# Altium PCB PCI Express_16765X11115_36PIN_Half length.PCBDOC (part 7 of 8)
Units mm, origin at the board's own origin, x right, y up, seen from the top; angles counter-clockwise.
Board outline 178 x 110.97 mm, 10 copper layers (Top Layer, Int1 (GND), Int2 (Sign), Int3 (Sign), Int4 (PWR), Int5 (GND), Int6 (Sign), Int7 (Sign), Int8 (GND), Bottom Layer), stack 1.429 mm thick; 528 components, 525 nets, 2272 pads, 1491 vias.
Unrouted connection lines stored in the file: 373.
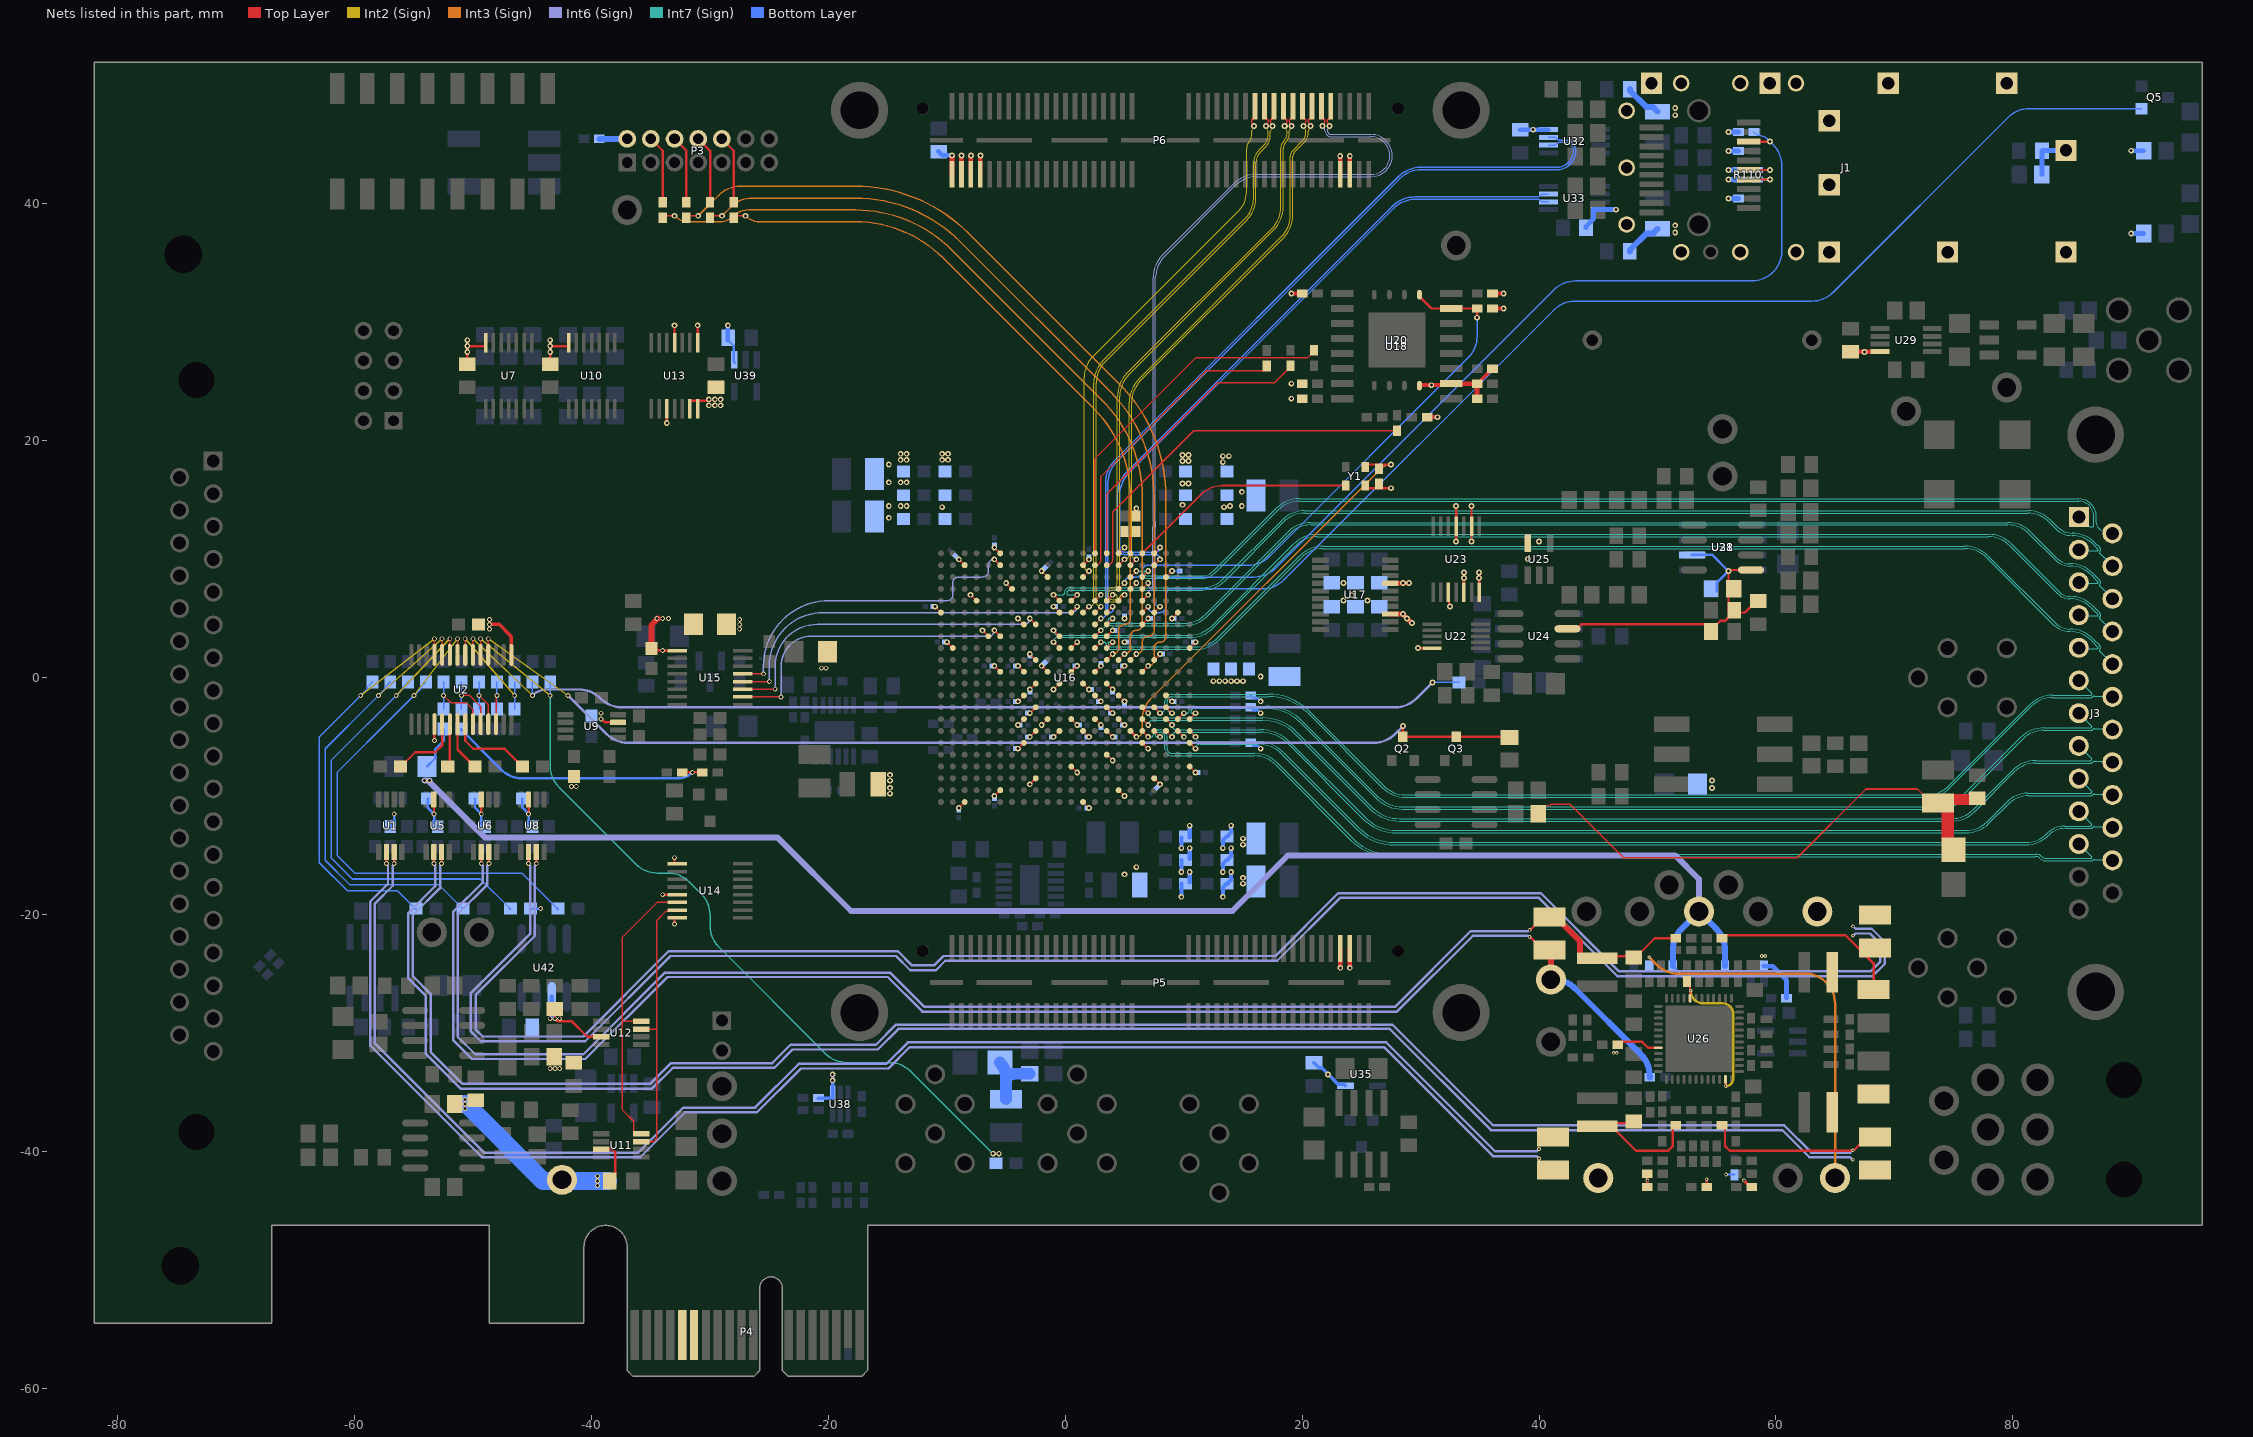
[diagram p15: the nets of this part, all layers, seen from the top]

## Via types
v1: diameter 0.483, hole 0.254, Top Layer to Bottom Layer, tented both sides, 740 vias
v2: diameter 0.508, hole 0.254, Top Layer to Bottom Layer, tented both sides, 302 vias
v3: diameter 0.406, hole 0.254, Top Layer to Bottom Layer, tented both sides, 267 vias
v4: diameter 0.305, hole 0.152, Top Layer to Bottom Layer, tented both sides, 95 vias
v5: diameter 0.5, hole 0.254, Top Layer to Bottom Layer, tented both sides, 50 vias
v6: diameter 0.45, hole 0.254, Top Layer to Bottom Layer, tented both sides, 23 vias
v7: diameter 0.6, hole 0.254, Top Layer to Bottom Layer, tented both sides, 14 vias

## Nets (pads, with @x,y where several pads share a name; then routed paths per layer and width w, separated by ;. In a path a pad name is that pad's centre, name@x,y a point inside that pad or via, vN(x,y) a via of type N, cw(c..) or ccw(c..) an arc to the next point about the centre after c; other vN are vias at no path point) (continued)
S49_64.S60_P: P6.56 U16.N20 | length 46
  Top Layer w0.127: U16.N20@1.5,8.5 v1(2,9) ; v2(15.912,46.6) ccw(c15.732,46.6) 15.859,46.727 15.817,46.77 cw(c16.046,47) 15.721,47 15.721,47.04 cw(c15.873,47.04) 15.766,47.148 cw(c15.838,47.076) 15.838,47.178 ccw(c15.838,47.28) 15.91,47.208 15.95,47.248 ccw(c15.781,47.416) 16.02,47.416 P6.56@16.02,48.245
  Int2 (Sign) w0.076: v1(2,9) cw(c2,9.398) 1.602,9.398 1.602,23.883 1.6,23.884 1.6,25.361 cw(c4.14,25.361) 2.344,27.157 14.679,39.492 ccw(c13.172,40.999) 15.303,40.999 15.303,44.725 cw(c15.975,44.725) 15.5,45.2 15.501,45.201 ccw(c14.97,45.732) 15.721,45.732 15.721,46.14 cw(c16.203,46.14) 15.862,46.48 ccw(c15.743,46.6) v2(15.912,46.6)
S49_64.S61_N: P6.60 U16.P17 | length 49.2
  Top Layer w0.127: U16.P17@2.5,5.5 v1(3,6) ; v2(17.512,46.6) ccw(c17.332,46.6) 17.459,46.727 17.417,46.77 cw(c17.647,47) 17.321,47 17.321,47.04 cw(c17.474,47.04) 17.366,47.148 cw(c17.438,47.076) 17.438,47.178 ccw(c17.438,47.28) 17.51,47.208 17.55,47.248 ccw(c17.381,47.416) 17.62,47.416 P6.60@17.62,48.245
  Int2 (Sign) w0.076: v1(3,6) cw(c3,6.398) 2.602,6.398 2.602,12.5 2.6,12.5 2.6,24.861 cw(c5.14,24.861) 3.344,26.657 15.331,38.644 ccw(c13.475,40.5) 16.1,40.496 ccw(c13.475,40.5) 16.1,40.5 16.1,43.5 cw(c17.338,43.5) 16.462,44.375 16.975,44.888 ccw(c16.14,45.724) 17.321,45.724 17.321,46.14 cw(c17.803,46.14) 17.462,46.48 ccw(c17.343,46.6) v2(17.512,46.6)
S49_64.S61_P: P6.58 U16.N17 | length 49.3
  Top Layer w0.127: U16.N17@1.5,5.5 v1(2,6) ; P6.58@16.82,48.245 16.82,47.416 ccw(c17.058,47.416) 16.89,47.248 16.93,47.208 ccw(c17.002,47.28) 17.002,47.178 cw(c17.002,47.076) 17.074,47.148 cw(c16.966,47.04) 17.118,47.04 17.118,47 cw(c16.793,47) 17.023,46.77 16.98,46.727 ccw(c17.107,46.6) v2(16.928,46.6)
  Int2 (Sign) w0.076: v1(2,6) ccw(c2,6.398) 2.398,6.398 2.398,12.469 ; 2.398,12.471 ccw(c2.322,12.47) 2.398,12.478 cw(c2.6,12.5) 2.397,12.5 2.397,24.862 cw(c5.137,24.862) 3.2,26.8 15.187,38.787 ccw(c13.475,40.5) 15.897,40.5 ; 15.897,40.449 15.897,43.501 cw(c17.335,43.501) 16.318,44.518 16.831,45.031 ccw(c16.14,45.724) 17.118,45.724 17.118,46.14 ccw(c16.637,46.14) 16.977,46.48 cw(c17.097,46.6) v2(16.928,46.6)
S49_64.S62_N: P6.62 U16.T18 | length 50.7
  Top Layer w0.127: U16.T18@4.5,6.5 v1(5,7) ; P6.62@18.42,48.245 18.42,47.416 ccw(c18.658,47.416) 18.489,47.248 18.529,47.208 ccw(c18.601,47.28) 18.601,47.178 cw(c18.601,47.076) 18.673,47.148 cw(c18.566,47.04) 18.718,47.04 18.718,47 cw(c18.393,47) 18.623,46.77 18.58,46.727 ccw(c18.707,46.6) v2(18.528,46.6)
  Int2 (Sign) w0.076: v1(5,7) 4.802,7 ccw(c4.802,6.8) 4.602,6.8 cw(c4.198,6.8) 4.198,6.397 4,6.397 cw(c4,7) 3.397,7 cw(c4,7) 4,7.603 4.003,7.603 ccw(c4.003,8) 4.4,8 4.4,23.765 cw(c7.141,23.765) 5.191,25.69 cw(c7.141,23.765) 5.202,25.702 ; 5.203,25.703 17.453,37.953 ccw(c15.657,39.749) 18.197,39.749 18.197,44.671 cw(c19.225,44.671) 18.498,45.398 18.519,45.419 ccw(c18.037,45.9) 18.718,45.9 18.718,46.14 ccw(c18.237,46.14) 18.577,46.48 cw(c18.697,46.6) v2(18.528,46.6)
S49_64.S62_P: P6.64 U16.R18 | length 50.1
  Top Layer w0.127: U16.R18@3.5,6.5 v1(4,7) ; v2(19.112,46.6) ccw(c18.932,46.6) 19.059,46.727 19.017,46.77 cw(c19.246,47) 18.921,47 18.921,47.04 cw(c19.073,47.04) 18.966,47.148 cw(c19.038,47.076) 19.038,47.178 ccw(c19.038,47.28) 19.11,47.208 19.15,47.248 ccw(c18.981,47.416) 19.22,47.416 P6.64@19.22,48.245
  Int2 (Sign) w0.076: v1(4,7) 4.198,7 cw(c4.198,6.8) 4.398,6.8 cw(c4.198,6.8) 4.198,6.6 4,6.6 cw(c4,7) 3.6,7 cw(c4,7) 4,7.4 4.003,7.4 ccw(c4.003,8) 4.603,8 4.603,23.764 cw(c7.143,23.764) 5.347,25.56 17.597,37.81 ccw(c15.659,39.748) 18.4,39.748 18.4,44.668 cw(c19.232,44.668) 18.644,45.256 18.663,45.275 ccw(c18.038,45.9) 18.921,45.9 18.921,46.14 cw(c19.403,46.14) 19.062,46.48 ccw(c18.943,46.6) v2(19.112,46.6)
S49_64.S63_N: P6.68 U16.U21 | length 45.3
  Top Layer w0.127: U16.U21@5.5,9.5 v1(6,10) ; v2(20.712,46.6) ccw(c20.532,46.6) 20.659,46.727 20.617,46.77 cw(c20.847,47) 20.521,47 20.521,47.04 cw(c20.674,47.04) 20.566,47.148 cw(c20.638,47.076) 20.638,47.178 ccw(c20.638,47.28) 20.71,47.208 20.75,47.248 ccw(c20.581,47.416) 20.82,47.416 P6.68@20.82,48.245
  Int2 (Sign) w0.076: v1(6,10) cw(c6,10.398) 5.602,10.398 5.602,23.262 cw(c8.142,23.262) 6.344,25.057 cw(c8.142,23.262) 6.346,25.058 18.4,37.113 ccw(c16.463,39.051) 19.203,39.051 19.203,44 cw(c19.774,44) 19.37,44.403 20.208,45.241 ccw(c19.45,45.998) 20.521,45.998 20.521,46.14 cw(c21.003,46.14) 20.662,46.48 ccw(c20.543,46.6) v2(20.712,46.6)
S49_64.S63_P: P6.66 U16.T21 | length 45.3
  Top Layer w0.127: U16.T21@4.5,9.5 v1(5,10) ; P6.66@20.02,48.245 20.02,47.416 ccw(c20.258,47.416) 20.09,47.248 20.13,47.208 ccw(c20.202,47.28) 20.202,47.178 cw(c20.202,47.076) 20.274,47.148 cw(c20.166,47.04) 20.318,47.04 20.318,47 cw(c19.993,47) 20.223,46.77 20.18,46.727 ccw(c20.307,46.6) v2(20.128,46.6)
  Int2 (Sign) w0.076: v1(5,10) ccw(c5,10.398) 5.398,10.398 5.398,23.278 cw(c8.103,23.278) 6.19,25.19 ; 6.197,25.197 18.256,37.256 ccw(c16.46,39.052) 19,39.052 19,44.001 cw(c19.771,44.001) 19.226,44.546 20.063,45.383 ccw(c19.446,46) 20.318,46 20.318,46.14 ccw(c19.837,46.14) 20.177,46.48 cw(c20.297,46.6) v2(20.128,46.6)
S49_64.S64_N: P6.70 U16.V19 | length 61.4
  Top Layer w0.127: U16.V19@6.5,7.5 v1(7,8) ; P6.70@21.62,48.245 21.62,47.416 ccw(c21.858,47.416) 21.689,47.248 21.729,47.208 ccw(c21.801,47.28) 21.801,47.178 cw(c21.801,47.076) 21.873,47.148 cw(c21.766,47.04) 21.918,47.04 21.918,47 cw(c21.593,47) 21.823,46.77 21.78,46.727 ccw(c21.907,46.6) v2(21.728,46.6)
  Int6 (Sign) w0.076: v1(7,8) 7,7.802 ccw(c7.2,7.802) 7.2,7.602 ccw(c7.2,7.802) 7.4,7.802 7.4,12.69 cw(c20.914,12.69) 7.408,13.156 7.408,33.76 cw(c10.149,33.76) 8.211,35.698 14.225,41.713 cw(c16.163,39.775) 16.163,42.516 25.853,42.516 ccw(c25.853,44.063) 27.4,44.063 ccw(c25.786,44.063) 25.786,45.676 22.448,45.676 cw(c22.448,46.2) 21.924,46.2 ccw(c21.602,46.2) 21.83,46.428 21.777,46.48 cw(c21.897,46.6) v2(21.728,46.6)
S49_64.S64_P: P6.72 U16.V18 | length 61.7
  Top Layer w0.127: U16.V18@6.5,6.5 v1(7,7) ; v2(22.312,46.6) ccw(c22.132,46.6) 22.259,46.727 22.216,46.77 cw(c22.446,47) 22.121,47 22.121,47.04 cw(c22.273,47.04) 22.166,47.148 cw(c22.238,47.076) 22.238,47.178 ccw(c22.238,47.28) 22.31,47.208 22.35,47.248 ccw(c22.181,47.416) 22.42,47.416 P6.72@22.42,48.245
  Int6 (Sign) w0.076: v1(7,7) 7,7.198 cw(c7.2,7.198) 7.2,7.398 ccw(c7.2,7.802) 7.603,7.802 7.603,12.689 cw(c20.917,12.689) 7.611,13.156 7.611,33.759 cw(c10.151,33.759) 8.355,35.555 14.368,41.568 cw(c16.164,39.772) 16.164,42.312 25.577,42.312 ; v2(22.312,46.6) cw(c22.128,46.6) 22.258,46.47 22.226,46.438 ccw(c22.464,46.2) 22.127,46.2 ccw(c22.448,46.2) 22.448,45.879 25.786,45.879 cw(c25.786,44.063) 27.603,44.063 cw(c25.853,44.063) 25.853,42.312 25.584,42.312
SCL: J1.5 R110.1 | length 2.9
  Top Layer w0.203: J1.5@57.7,42.87 v1(59.5,42.87)
  Bottom Layer w0.203: R110.1@58.45,42.87 v1(59.5,42.87)
SCLK: U11.8 U12.8 U14.14 | length 27.5
  Top Layer w0.127: U11.8@-35.8,-38.5 -36.3,-38.5 -36.437,-38.363 -36.437,-37.463 -37.4,-36.5 -37.4,-26.525 ; U12.8@-35.8,-29.025 -37.4,-29.025 -37.4,-26.525 ; U14.14@-32.775,-18.975 -34.475,-18.975 -37.4,-21.9 -37.4,-26.525
SDA: J1.4 R110.2 | length 2.9
  Top Layer w0.203: J1.4@57.7,42.07 v1(59.5,42.07)
  Bottom Layer w0.203: R110.2@58.45,42.07 v1(59.5,42.07)
SENS1: R5.2 U2.19 | length 6.2
  Top Layer w0.203: R5.2@-56.2,-7.6 -54.9,-6.3 -53.2,-6.3 -52.625,-5.725 U2.19@-52.625,-3.925
SENS2: R6.2 U2.20 | length 3.7
  Top Layer w0.203: R6.2@-52.15,-7.5 -51.975,-7.325 U2.20@-51.975,-3.925 U2.20@-52,-3.9
SENS3: R10.2 U2.21 | length 4.2
  Top Layer w0.203: U2.21@-51.325,-3.925 -51.325,-6.075 R10.2@-49.9,-7.5
SENS4: R12.2 U2.22 | length 7.2
  Top Layer w0.203: U2.22@-50.675,-3.925 -50.672,-3.928 -50.672,-5.328 -50,-6 -47.35,-6 -46.298,-7.052 -46.298,-7.102 -45.9,-7.5 R12.2@-45.85,-7.5
SENS5: R189.2 R190.1 U2.23 | length 6.5
  Top Layer w0.127: v3(-52.5,-1.5) -51.9,-2.1 -50.6,-2.1 -50.025,-2.675 U2.23@-50.025,-3.925
  Bottom Layer w0.127: R189.2@-52.5,-2.65 v3(-52.5,-1.5) R190.1@-52.5,-0.35
SENS6: R186.2 R187.1 U2.24 | length 5.8
  Top Layer w0.127: v3(-51,-1.5) -50.3,-1.5 -49.375,-2.425 U2.24@-49.375,-3.925
  Bottom Layer w0.127: R186.2@-51,-2.65 v3(-51,-1.5) R187.1@-51,-0.35
SENS7: R181.2 R182.1 U2.25 | length 5
  Top Layer w0.127: v3(-49.5,-1.5) -48.725,-2.275 U2.25@-48.725,-3.925
  Bottom Layer w0.127: R181.2@-49.5,-2.65 v3(-49.5,-1.5) R182.1@-49.5,-0.35
SENS8: R175.2 R176.1 U2.26 | length 4.7
  Top Layer w0.127: U2.26@-48.037,-3.837 -48.037,-1.537 v3(-48,-1.5)
  Bottom Layer w0.127: R175.2@-48,-2.65 v3(-48,-1.5) R176.1@-48,-0.35
SENS9: R192.2 R200.1 U2.11 | length 36.1
  Top Layer w0.127: U2.11@-53.275,1.925 v3(-53.275,3.287)
  Int2 (Sign) w0.127: v3(-59.5,-1.5) v3(-53.275,3.287)
  Bottom Layer w0.127: R200.1@-58.5,-0.35 -58.937,-0.787 -58.937,-0.937 -63,-5 -63,-7.5 -63,-15.621 -60.621,-18 -56.4,-18 R192.2@-54.9,-19.5
  Bottom Layer w0.203: R192.2@-54.9,-19.5 R192.2@-54.85,-19.5
SENS10: R180.2 R198.1 U2.10 | length 39.2
  Top Layer w0.127: U2.10@-52.625,1.925 v3(-52.625,3.287)
  Int2 (Sign) w0.127: v3(-58,-1.5) v3(-52.625,3.287)
  Bottom Layer w0.127: R198.1@-57,-0.35 -57.437,-0.787 -57.437,-0.937 -58.5,-2 -62.5,-6 -62.5,-15.414 -60.414,-17.5 -52.9,-17.5 R180.2@-50.9,-19.5
  Bottom Layer w0.203: R180.2@-50.9,-19.5 R180.2@-50.85,-19.5
SENS11: R168.2 R195.1 U2.9 | length 42.4
  Top Layer w0.127: U2.9@-51.975,1.925 v3(-51.975,3.287)
  Int2 (Sign) w0.127: v3(-56.5,-1.5) v3(-51.975,3.287)
  Bottom Layer w0.127: R195.1@-55.5,-0.35 -55.937,-0.787 -55.937,-0.937 -62,-7 -62,-8.3 -62,-15.207 -60.207,-17 -49.4,-17 R168.2@-46.9,-19.5
  Bottom Layer w0.203: R168.2@-46.9,-19.5 R168.2@-46.85,-19.5
SENS12: R159.2 R193.1 U2.8 | length 45.7
  Top Layer w0.127: U2.8@-51.325,1.925 v3(-51.325,3.287)
  Int2 (Sign) w0.127: v3(-55,-1.5) v3(-51.325,3.287)
  Bottom Layer w0.127: R193.1@-54,-0.35 -54.437,-0.787 -54.437,-0.937 -56.5,-3 -61.5,-8 -61.5,-15 -60,-16.5 -45.9,-16.5 R159.2@-42.9,-19.5
  Bottom Layer w0.203: R159.2@-42.9,-19.5 R159.2@-42.85,-19.5
SENS13: R170.2 R171.1 U2.7 | length 10
  Top Layer w0.127: U2.7@-50.675,1.925 v3(-50.675,3.287)
  Int2 (Sign) w0.127: v3(-50.675,3.287) v3(-46.5,-1.5)
  Bottom Layer w0.127: R170.2@-46.5,-2.65 v3(-46.5,-1.5) R171.1@-46.5,-0.35
SENS14: R129.2 R166.1 U2.6 | length 89.2
  Top Layer w0.127: U2.6@-50.025,1.925 v3(-50.025,3.287)
  Int6 (Sign) w0.203: v3(-45,-1.5) cw(c-43.793,-2.707) -43.793,-1 -41.052,-1 cw(c-41.052,-3.54) -39.258,-1.742 cw(c-41.052,-3.54) -39.256,-1.744 ; -39.4,-1.6 -39.256,-1.744 ; v2(31,-0.4) 29.644,-1.756 cw(c27.848,0.04) 27.848,-2.5 -37.448,-2.5 cw(c-37.448,0.04) -39.244,-1.756 -39.256,-1.744
  Int2 (Sign) w0.127: v3(-50.025,3.287) v3(-45,-1.5)
  Bottom Layer w0.127: v3(-45,-1.5) R166.1@-45,-0.35 ; v2(31,-0.4) R129.2@33.25,-0.4
SENS15: R141.2 R162.1 U2.5 | length 69.1
  Top Layer w0.127: U2.5@-49.375,1.925 v3(-49.375,3.287)
  Int2 (Sign) w0.127: v3(-49.375,3.287) v3(-43.5,-1.5)
  Int7 (Sign) w0.127: v3(-43.5,-1.5) -43.5,-7.448 ccw(c-40.96,-7.448) -42.756,-9.244 -36.244,-15.756 ccw(c-34.448,-13.96) -34.448,-16.5 -33.552,-16.5 cw(c-33.552,-19.04) -31.756,-17.244 -30.744,-18.256 cw(c-32.54,-20.052) -30,-20.052 -30,-20.948 ccw(c-27.46,-20.948) -29.256,-22.744 -20.244,-31.756 ccw(c-18.448,-29.96) -18.448,-32.5 -14.852,-32.5 cw(c-14.852,-35.04) -13.056,-33.244 v6(-6.1,-40.2) v6(-5.6,-40.2)
  Bottom Layer w0.127: v3(-43.5,-1.5) R162.1@-43.5,-0.35
SENS16: Q2.3 Q3.3 R45.2 U2.4 | length 92
  Top Layer w0.127: U2.4@-48.725,1.925 v3(-48.725,3.287)
  Top Layer w0.203: v2(28.5,-4.1) Q2.3@28.5,-5 Q3.3@33,-5 R45.2@37.5,-5
  Int6 (Sign) w0.203: v3(-42,-1.5) -38.744,-4.756 ccw(c-36.948,-2.96) -36.948,-5.5 26.048,-5.5 ccw(c26.048,-2.96) 27.844,-4.756 v2(28.5,-4.1)
  Int2 (Sign) w0.127: v3(-48.725,3.287) v3(-42,-1.5)
SENSE.SENS_10_P: C68.1 L4.2 R77.2 R96.1 U5.3 | length 161.1
  Top Layer w0.203: v3(-52.675,-15.7) U5.3@-52.675,-14.725 ; R77.2@55.5,-37.75 55.7,-37.95 55.7,-39.55 56.1,-39.95 66.55,-39.95 67.014,-39.486 67.127,-39.486 67.821,-38.791 R96.1@67.821,-38.678
  Int6 (Sign) w0.203: v3(-52.675,-15.7) -52.675,-15.755 -52.8,-15.88 -52.8,-17.766 -55.1,-20.066 -55.1,-25.2 -53.6,-26.7 -53.6,-31.6 -50.9,-34.3 -35.066,-34.3 -33.312,-32.546 -24.746,-32.546 -23.2,-31 -16,-31 -14.3,-29.3 27.6,-29.3 36.1,-37.8 60.7,-37.8 63,-40.1 66.272,-40.1 66.472,-39.9 v4(66.5,-39.9)
SENSE.SENS_18_P: C46.2 L3.2 R48.1 R68.2 U6.3 | length 129.5
  Top Layer w0.203: v3(-48.675,-15.7) U6.3@-48.675,-14.725 ; v4(39.2,-21.3) 39.219,-21.281 39.269,-21.281 40.35,-20.2 R48.1@40.9,-20.2 ; L3.2@45.973,-23.523 47.875,-23.523 48,-23.648 48.125,-23.648 49.773,-22 51.6,-22 R68.2@51.6,-22.25
  Top Layer w0.5: R48.1@40.9,-20.2 41.45,-20.2 42,-20.75 42,-20.8 43.472,-22.272 43.472,-23.45 43.712,-23.69 L3.2@44.922,-23.69
  Int6 (Sign) w0.203: v3(-48.675,-15.7) -48.675,-15.754 -48.8,-15.879 -48.8,-17.466 -51.3,-19.966 -51.3,-30.334 -49.834,-31.8 -40.7,-31.8 -33.8,-24.9 -14.8,-24.9 -11.9,-27.8 27.832,-27.8 34.232,-21.4 38.5,-21.4 39.073,-21.4 39.173,-21.3 v4(39.2,-21.3)
SENSE.SENS_25_P: C69.2 L5.2 R78.2 R97.1 U8.3 | length 165.9
  Top Layer w0.203: v3(-44.675,-15.7) U8.3@-44.675,-14.725 ; R78.2@55.4,-22 55.4,-21.75 65.875,-21.75 68.25,-24.125 C69.2@68.25,-26.35 ; R78.2@55.45,-22.25 R78.2@55.45,-22
  Int6 (Sign) w0.203: v3(-44.675,-15.7) -44.675,-15.754 -44.8,-15.879 -44.8,-21.8 -49.8,-26.8 -49.8,-29.7 -49.2,-30.3 -40.7,-30.3 -33.5,-23.1 -14.134,-23.1 -12.934,-24.3 -11.1,-24.3 -10.3,-23.5 17.734,-23.5 23.034,-18.2 40.166,-18.2 46.766,-24.8 68,-24.8 68.8,-24 68.8,-22.466 67.934,-21.6 66.728,-21.6 66.528,-21.8 v4(66.5,-21.8)
SENSE.SENS_33_P: C45.2 L2.2 R49.1 R67.2 U1.3 | length 139
  Top Layer w0.203: v3(-56.675,-15.7) U1.3@-56.675,-14.725 ; L2.2@44.237,-38.259 44.646,-37.85 46.102,-37.85 48.2,-39.948 48.2,-39.95 50.9,-39.95 51.3,-39.55 51.3,-38.048 51.599,-37.75 R67.2@51.6,-37.75 ; L2.2@45.973,-37.626 47.848,-37.626 C45.2@48,-37.475
  Int6 (Sign) w0.203: v3(-56.675,-15.7) -56.675,-15.754 -56.8,-15.879 -56.8,-17.566 -58.3,-19.066 -58.3,-30.9 -49.1,-40.1 -36.066,-40.1 -32.266,-36.3 -26.2,-36.3 -22.5,-32.6 -15.1,-32.6 -13.3,-30.8 27.1,-30.8 36.3,-40 39.773,-40 39.973,-39.8 v4(40,-39.8)
SENSE.SENS_120b_P: D2.2 R139.1 R142.1 | length 5.3
  Bottom Layer w1: D2.2@-5.525,-32.5 cw(c-6.792,-33.767) -5,-33.767 ; R142.1@-5,-35.6 -5,-33.767 ; R139.1@-3,-33.45 -4.234,-33.45 ccw(c-4.234,-34.534) -5,-33.767
SENSE.SENS_120x_P: C73.1 D1.2 R46.2 R99.1 | length 46.7
  Top Layer w0.127: R46.2@39.9,-11.5 39.9,-11.45 40.537,-10.813 40.886,-10.813 41,-10.7 42.634,-10.7 47.134,-15.2 61.8,-15.2 67.6,-9.4 71.95,-9.4 73.15,-10.6 R99.1@73.7,-10.6
  Top Layer w0.925: R99.1@74.021,-10.279 76.896,-10.279 C73.1@77,-10.175
  Top Layer w1.07: R99.1@73.7,-10.6 74.25,-10.6 74.515,-10.865 74.515,-14.04 D1.2@75,-14.525
SFP_SH: C75.1 J1.21 J1.22 R107.1 | length 4
  Bottom Layer w0.406: R107.1@82.45,42.5 82.475,42.525 82.475,44.475 82.52,44.52 J1.21@84.5,44.52
SFPIN.LEDIN: Q5.1 U16.V17 | length 102.8
  Top Layer w0.127: U16.V17@6.5,5.5 v1(7,6)
  Bottom Layer w0.127: v1(7,6) ccw(c7.5,6) 7.5,5.5 8,5.5 ccw(c8,6) 8.5,6 8.5,7 cw(c9,7) 9,7.5 16.648,7.5 ccw(c16.648,10.04) 18.444,8.244 41.256,31.056 cw(c43.052,29.26) 43.052,31.8 63.048,31.8 ccw(c63.048,34.34) 64.844,32.544 79.606,47.306 cw(c81.402,45.51) 81.402,48.05 Q5.1@90.875,48.05
SFPIN.LOS: J1.8 R113.1 U16.W17 | length 80.9
  Top Layer w0.127: U16.W17@7.5,5.5 v1(8,6)
  Top Layer w0.203: J1.8@57.7,45.27 v1(59.5,45.27)
  Bottom Layer w0.127: v1(8,6) cw(c8,6.5) 7.5,6.5 7.5,8 cw(c8,8) 8,8.5 15.948,8.5 ccw(c15.948,11.04) 17.744,9.244 20,11.5 37.9,29.4 41.256,32.756 cw(c43.052,30.96) 43.052,33.5 57.96,33.5 ; 58,33.5 57.96,33.5 ; R113.1@58.15,46.07 58.436,45.784 58.589,45.784 cw(c58.589,44.823) 59.268,45.502 v1(59.5,45.27) 59.756,45.014 cw(c57.96,43.218) 60.5,43.218 60.5,36.04 cw(c57.96,36.04) 57.96,33.5
SFPIN.SYNCIN_N: U16.R17 U32.7 | length 67
  Top Layer w0.127: U16.R17@3.5,5.5 v1(4,6)
  Bottom Layer w0.127: v1(4,6) 4,5.7 cw(c3.8,5.7) 3.8,5.5 cw(c3.8,5.698) 3.602,5.698 3.602,16.45 cw(c6.142,16.45) 4.346,18.246 28.253,42.153 cw(c30.049,40.357) 30.049,42.897 41.5,42.897 ccw(c41.5,44.5) 43.103,44.5 ccw(c42.202,44.5) 42.202,45.402 41.721,45.402 cw(c41.721,45.656) 41.542,45.476 41.542,45.479 41.468,45.552 ccw(c41.291,45.375) 41.291,45.625 U32.7@40.805,45.625
SFPIN.SYNCIN_P: U16.P16 U32.6 | length 66.7
  Top Layer w0.127: U16.P16@2.5,4.5 v1(3,5)
  Bottom Layer w0.127: v1(3,5) ccw(c3,5.398) 3.398,5.398 3.398,16.451 cw(c6.139,16.451) 4.201,18.389 28.11,42.297 cw(c30.048,40.359) 30.048,43.1 41.5,43.1 ccw(c41.5,44.5) 42.9,44.5 ccw(c42.202,44.5) 42.202,45.198 41.721,45.198 ccw(c41.721,44.944) 41.542,45.124 41.542,45.121 41.468,45.048 cw(c41.291,45.225) 41.291,44.975 U32.6@40.805,44.975
SFPIN.SYNCOUT_N: U16.W22 U33.2 | length 56
  Top Layer w0.127: U16.W22@7.5,10.5 v1(8,11)
  Bottom Layer w0.127: v1(8,11) cw(c7.602,11) 7.602,10.602 5,10.602 cw(c5,11.002) 4.6,11.002 4.6,15.448 cw(c7.14,15.448) 5.344,17.244 27.754,39.654 cw(c29.551,37.858) 29.551,40.398 39.879,40.398 cw(c39.879,40.144) 40.059,40.324 40.059,40.321 40.132,40.248 ccw(c40.309,40.425) 40.309,40.175 U33.2@40.795,40.175
SFPIN.SYNCOUT_P: U16.W21 U33.3 | length 56.6
  Top Layer w0.127: U16.W21@7.5,9.5 v1(8,10)
  Bottom Layer w0.127: v1(8,10) ccw(c7.602,10) 7.602,10.398 5,10.398 cw(c5,11.002) 4.397,11.002 4.397,15.449 cw(c7.137,15.449) 5.2,17.387 27.612,39.799 cw(c29.549,37.861) 29.549,40.602 39.879,40.602 ccw(c39.879,40.856) 40.059,40.676 40.059,40.679 40.132,40.752 cw(c40.309,40.575) 40.309,40.825 U33.3@40.795,40.825
SMCLK: P4.B5
SMDAT: P4.B6
SQSPI.EMCLK_EN: R38.2 U16.U7 Y1.1 | length 35.1
  Top Layer w0.203: U16.U7@5.5,-4.5 v1(6,-5) ; Y1.1@25.3,17.9 25.4,18 v1(27.5,18)
  Int3 (Sign) w0.127: v1(6,-5) ccw(c6,-4.5) 6.5,-4.5 6.5,-3.552 cw(c9.04,-3.552) 7.244,-1.756 26.646,17.646 cw(c27.5,16.793) v1(27.5,18)
SQSPI.PUDC_B: R28.1 R29.1 U16.U22 | length 2.6
  Top Layer w0.127: R28.1@5.1,12.15 5.5,11.75 ; U16.U22@5.5,10.5 5.5,11.75 ; R29.1@6,12.3 6,12.25 5.5,11.75
SQSPI.QSPI_CS: R42.2 U16.T19 U18.7 U20.1 | length 47.5
  Top Layer w0.127: U16.T19@4.5,7.5 v1(5,8)
  Top Layer w0.203: U20.1@29.905,32.34 29.905,32.193 30.923,31.175 U18.7@32.6,31.175 R42.2@34.77,31.175 34.77,30.473 ccw(c34.873,30.473) v1@34.8,30.4
  Bottom Layer w0.127: v1(5,8) cw(c5.5,8) 5.5,8.5 6,8.5 ccw(c6,9) 6.5,9 cw(c7,9) 7,9.5 15.448,9.5 ccw(c15.448,12.04) 17.244,10.244 34.026,27.026 ccw(c32.23,28.822) 34.77,28.822 v1(34.77,30.4)
SQSPI.QSPI_DQ0: R35.2 U16.P22 | length 30.4
  Top Layer w0.127: U16.P22@2.5,10.5 2.5,13.156 2.5,18.5 11,27 20.45,27 21.1,27.65 R35.2@21.1,27.7
SQSPI.QSPI_DQ1: R31.2 U16.R22 | length 25.1
  Top Layer w0.127: U16.R22@3.5,10.5 3.5,13.156 3.5,15.5 12.9,24.9 17.667,24.9 18.726,25.959 19.012,26.245 R31.2@19.012,26.345
SQSPI.QSPI_DQ2: R30.2 U16.P21 | length 25.5
  Top Layer w0.127: U16.P21@2.5,9.5 ccw(c2.5,10) 3,10 3,13.156 3,17 11.936,25.936 16.963,25.936 R30.2@16.967,25.94
SQSPI.QSPI_DQ3: R39.2 U16.R21 | length 31.6
  Top Layer w0.127: U16.R21@3.5,9.5 ccw(c3.5,10) 4,10 4,13.156 4,14 10.85,20.85 R39.2@28,20.85
SQSPI.QSPI_EMCLK: U16.V22 Y1.3 | length 19.4
  Top Layer w0.127: U16.V22@6.5,10.5 11.484,15.484 cw(c13.28,13.688) 13.28,16.228 Y1.3@23.668,16.228
SQSPI.XMUX0: U15.13 U16.F21 | length 28.4
  Top Layer w0.127: U15.13@-27.225,0.325 v3(-25.5,0.325) ; v1(-6,10) U16.F21@-5.5,9.5
  Int6 (Sign) w0.127: v3(-25.5,0.325) -25.5,0.96 cw(c-19.96,0.96) -19.96,6.5 -10,6.5 ccw(c-10,7) -9.5,7 -9.5,8 cw(c-9,8) -9,8.5 -7,8.5 ccw(c-7,9) -6.5,9 -6.5,9.5 cw(c-6,9.5) v1(-6,10)
SQSPI.XMUX1: U15.12 U16.M17 | length 33.1
  Top Layer w0.127: U15.12@-27.225,-0.325 v3(-25,-0.325) ; U16.M17@0.5,5.5 v1(1,6)
  Int6 (Sign) w0.127: v3(-25,-0.325) -25,0.96 cw(c-20.46,0.96) -20.46,5.5 0.5,5.5 ccw(c0.5,6) v1(1,6)
SQSPI.XMUX2: U15.11 U16.J16 | length 29.2
  Top Layer w0.127: U15.11@-27.225,-0.975 v3(-24.5,-0.975) ; v1(-3,5) U16.J16@-2.5,4.5
  Int6 (Sign) w0.127: v3(-24.5,-0.975) -24.5,0.96 cw(c-20.96,0.96) -20.96,4.5 -3.5,4.5 ccw(c-3.5,5) v1(-3,5)
SQSPI.XMUX3: U15.10 U16.F15 | length 26.3
  Top Layer w0.127: U15.10@-27.225,-1.625 v3(-24,-1.625) ; v1(-6,4) U16.F15@-5.5,3.5
  Int6 (Sign) w0.127: v3(-24,-1.625) -24,0.96 cw(c-21.46,0.96) -21.46,3.5 -6.5,3.5 ccw(c-6.5,4) v1(-6,4)
SYNC: U11.7 U12.7 U14.15 | length 23.2
  Top Layer w0.127: U11.7@-35.8,-39.175 -34.775,-39.175 -34.5,-38.9 -34.5,-27.175 -34.5,-20.5 -33.712,-19.712 -33.611,-19.712 -32.862,-19.711 U14.15@-32.775,-19.625 ; U12.7@-35.8,-29.675 -34.5,-29.675
T1_11.T1_N: J3.14 U16.V20 | length 87.5
  Top Layer w0.127: U16.V20@6.5,8.5 v1(7,9)
  Int7 (Sign) w0.076: v1(7,9) 6.702,9 ccw(c6.702,8.9) 6.602,8.9 ccw(c6.902,8.9) 6.902,8.6 11.5,8.6 ccw(c11.5,10.049) 12.524,9.024 17.802,14.302 cw(c19.737,12.366) 19.737,15.103 85.58,15.103 cw(c85.58,13.63) 87.053,13.63 87.053,13.092 ccw(c87.749,13.092) 87.257,12.6 ccw(c87.749,13.092) 87.749,12.396 87.911,12.396 cw(c87.911,11.677) J3.14@88.42,12.186
T1_11.T1_P: J3.1 U16.U20 | length 87.8
  Top Layer w0.127: U16.U20@5.5,8.5 v1(6,9)
  Int7 (Sign) w0.076: v1(6,9) 6.298,9 cw(c6.298,8.9) 6.398,8.9 ccw(c6.902,8.9) 6.902,8.397 11.503,8.397 ccw(c11.503,10.042) 12.666,8.879 17.943,14.156 cw(c19.739,12.36) 19.739,14.9 85.58,14.9 cw(c85.58,13.63) 86.85,13.63 86.85,12.835 ; J3.1@85.58,13.566 86.239,12.907 ccw(c86.596,13.264) 86.596,12.759 86.774,12.759 ccw(c86.774,12.835) 86.828,12.781 ccw(c86.774,12.835) 86.85,12.835 ; 86.85,13.073 86.85,12.835
T1_11.T2_N: J3.15 U16.L18 | length 94.9
  Top Layer w0.127: v1(-1,7) U16.L18@-0.5,6.5
  Int7 (Sign) w0.076: v1(-1,7) -0.202,7 ccw(c-0.202,7.1) -0.102,7.1 cw(c0.402,7.1) 0.402,7.603 11.551,7.603 ccw(c11.551,10.143) 13.347,8.347 18.302,13.302 cw(c20.237,11.366) 20.237,14.103 81.263,14.103 cw(c81.263,11.366) 83.198,13.302 83.793,12.707 ccw(c85.009,13.922) 85.009,12.203 cw(c85.009,9.462) 86.947,11.4 87.34,11.007 cw(c87.145,10.812) 87.421,10.812 ; 87.421,10.81 cw(c87.142,10.81) 87.339,10.613 ccw(c87.393,10.559) 87.317,10.559 ccw(c87.393,10.559) 87.339,10.505 J3.15@88.42,9.424
T1_11.T2_P: J3.2 U16.M18 | length 94.1
  Top Layer w0.127: U16.M18@0.5,6.5 v1(1,7)
  Int7 (Sign) w0.076: v1(1,7) 0.202,7 cw(c0.202,7.1) 0.102,7.1 cw(c0.402,7.1) 0.402,7.4 11.552,7.4 ccw(c11.552,10.141) 13.49,8.203 18.443,13.156 cw(c20.239,11.36) 20.239,13.9 81.261,13.9 cw(c81.261,11.36) 83.057,13.156 83.651,12.562 ccw(c85.007,13.918) 85.007,12 cw(c85.008,9.46) 86.804,11.256 87.196,10.864 cw(c87.142,10.81) 87.218,10.81 cw(c87.142,10.81) 87.196,10.756 cw(c87.142,10.81) 87.142,10.734 85.751,10.734 cw(c85.751,10.976) J3.2@85.58,10.805
T1_11.T3_N: J3.16 U16.R16 | length 92.2
  Top Layer w0.127: U16.R16@3.5,4.5 v1(4,5)
  Int7 (Sign) w0.076: v1(4,5) 3.8,5 ccw(c3.8,4.8) 3.6,4.8 ccw(c3.798,4.8) 3.798,4.602 10.049,4.602 ccw(c10.049,7.142) 11.846,5.346 18.802,12.302 cw(c20.737,10.366) 20.737,13.103 79.57,13.103 cw(c79.57,10.366) 81.505,12.302 83.723,10.083 ccw(c84.823,11.183) 84.823,9.628 cw(c84.823,6.887) 86.762,8.825 87.34,8.246 cw(c87.145,8.051) 87.421,8.051 ; 87.421,8.049 cw(c87.142,8.049) 87.339,7.852 ccw(c87.393,7.798) 87.317,7.798 ccw(c87.393,7.798) 87.339,7.744 J3.16@88.42,6.663
T1_11.T3_P: J3.3 U16.P15 | length 91.8
  Top Layer w0.127: U16.P15@2.5,3.5 v1(3,4)
  Int7 (Sign) w0.076: v1(3,4) cw(c3.962,3.038) 3.962,4.398 10.051,4.398 ccw(c10.051,7.139) 11.988,5.201 18.943,12.156 cw(c20.739,10.36) 20.739,12.9 79.567,12.9 cw(c79.567,10.36) 81.363,12.156 83.581,9.938 ccw(c84.822,11.179) 84.822,9.424 cw(c84.822,6.884) 86.618,8.681 87.196,8.103 cw(c87.142,8.049) 87.218,8.049 cw(c87.142,8.049) 87.196,7.995 cw(c87.142,8.049) 87.142,7.973 85.751,7.973 cw(c85.751,8.215) J3.3@85.58,8.044
T1_11.T4_N: J3.17 U16.L15 | length 97.1
  Top Layer w0.127: v1(-1,4) U16.L15@-0.5,3.5
  Int7 (Sign) w0.076: v1(-1,4) ccw(c-0.602,4) -0.602,3.602 10.55,3.602 ccw(c10.55,6.142) 12.346,4.346 19.302,11.302 cw(c21.237,9.366) 21.237,12.103 77.944,12.103 cw(c77.944,9.361) 79.883,11.3 83.958,7.225 ccw(c84.823,8.09) 84.823,6.867 cw(c84.823,4.126) 86.762,6.064 87.34,5.485 cw(c87.145,5.29) 87.421,5.29 ; 87.421,5.288 cw(c87.142,5.288) 87.339,5.091 ccw(c87.393,5.037) 87.317,5.037 ccw(c87.393,5.037) 87.339,4.983 J3.17@88.42,3.902
T1_11.T4_P: J3.4 U16.L14 | length 96.6
  Top Layer w0.127: v1(-1,3) U16.L14@-0.5,2.5
  Int7 (Sign) w0.076: v1(-1,3) cw(c-0.602,3) -0.602,3.398 10.551,3.398 ccw(c10.551,6.139) 12.489,4.201 19.443,11.156 cw(c21.239,9.36) 21.239,11.9 77.944,11.9 cw(c77.944,9.36) 79.74,11.156 83.815,7.081 ccw(c84.822,8.087) 84.822,6.663 cw(c84.822,4.123) 86.618,5.92 87.196,5.342 cw(c87.142,5.288) 87.218,5.288 cw(c87.142,5.288) 87.196,5.234 cw(c87.142,5.288) 87.142,5.212 85.751,5.212 cw(c85.751,5.454) J3.4@85.58,5.283
T1_11.T5_N: J3.18 U16.R14 | length 93.6
  Top Layer w0.127: U16.R14@3.5,2.5 v1(4,3)
  Int7 (Sign) w0.076: v1(4,3) 3.702,3 ccw(c3.702,2.9) 3.602,2.9 ccw(c3.902,2.9) 3.902,2.6 11.048,2.6 ccw(c11.048,5.14) 12.844,3.344 19.802,10.302 cw(c21.737,8.366) 21.737,11.103 75.965,11.103 cw(c75.965,8.361) 77.904,10.3 83.585,4.618 ccw(c84.823,5.856) 84.823,4.106 cw(c84.823,1.365) 86.762,3.303 87.34,2.724 cw(c87.145,2.529) 87.421,2.529 ; 87.421,2.527 cw(c87.142,2.527) 87.339,2.33 ccw(c87.393,2.276) 87.317,2.276 ccw(c87.393,2.276) 87.339,2.222 J3.18@88.42,1.142
T1_11.T5_P: J3.5 U16.P14 | length 93.4
  Top Layer w0.127: U16.P14@2.5,2.5 v1(3,3)
  Int7 (Sign) w0.076: v1(3,3) 3.298,3 cw(c3.298,2.9) 3.398,2.9 ccw(c3.902,2.9) 3.902,2.397 11.049,2.397 ccw(c11.049,5.137) 12.987,3.2 19.943,10.156 cw(c21.739,8.36) 21.739,10.9 75.964,10.9 cw(c75.964,8.36) 77.76,10.156 83.442,4.474 ccw(c84.822,5.854) 84.822,3.902 cw(c84.822,1.362) 86.618,3.159 87.196,2.581 cw(c87.142,2.527) 87.218,2.527 cw(c87.142,2.527) 87.196,2.473 cw(c87.142,2.527) 87.142,2.451 85.751,2.451 cw(c85.751,2.693) J3.5@85.58,2.522
T1_11.T6_N: J3.19 U16.Y9 | length 88.7
  Top Layer w0.127: U16.Y9@8.5,-2.5 v1(9,-3)
  Int2 (Sign) w0.076: v1@8.802,-3 v1(9,-3)
  Int7 (Sign) w0.076: v1(9,-3) cw(c9,-2.602) 8.602,-2.602 8.602,-1.998 cw(c9,-1.998) 9,-1.6 17.182,-1.6 cw(c17.182,-6.172) 20.415,-2.939 26.775,-9.3 ccw(c28.715,-7.36) 28.715,-10.103 72.762,-10.103 ccw(c72.762,-7.363) 74.7,-9.3 81.572,-2.428 cw(c83.368,-4.224) 83.368,-1.684 86.595,-1.684 ccw(c86.595,-1.453) 86.759,-1.617 cw(c86.922,-1.78) 86.922,-1.549 88.249,-1.549 cw(c88.249,-1.791) J3.19@88.42,-1.619
T1_11.T6_P: J3.6 U16.W9 | length 88.9
  Top Layer w0.127: U16.W9@7.5,-2.5 v1(8,-3)
  Int2 (Sign) w0.076: v1(8,-3) v1@8.198,-3
  Int7 (Sign) w0.076: v1(8,-3) ccw(c8,-2.602) 8.398,-2.602 8.398,-1.998 cw(c9,-1.998) 9,-1.397 17.182,-1.397 cw(c17.182,-6.172) 20.558,-2.795 26.919,-9.156 ccw(c28.715,-7.36) 28.715,-9.9 72.761,-9.9 ccw(c72.761,-7.36) 74.557,-9.156 81.429,-2.284 ; 81.429,-2.284 cw(c83.367,-4.222) 83.367,-1.481 86.53,-1.481 ccw(c86.53,-1.297) 86.661,-1.427 ccw(c86.607,-1.373) 86.683,-1.373 ccw(c86.607,-1.373) 86.661,-1.32 J3.6@85.58,-0.239
T1_11.T7_N: J3.20 U16.AB8 | length 84.9
  Top Layer w0.127: U16.AB8@10.5,-3.5 v1(11,-3)
  Int7 (Sign) w0.076: v1(11,-3) 10.702,-3 cw(c10.702,-2.9) 10.602,-2.9 cw(c10.902,-2.9) 10.902,-2.6 16.936,-2.6 cw(c16.936,-6.766) 19.881,-3.82 26.242,-10.181 ccw(c28.469,-7.954) 28.469,-11.103 73.793,-11.103 ccw(c73.793,-8.363) 75.731,-10.3 80.842,-5.189 cw(c82.638,-6.985) 82.638,-4.445 86.595,-4.445 ccw(c86.595,-4.214) 86.759,-4.378 cw(c86.922,-4.541) 86.922,-4.31 88.249,-4.31 cw(c88.249,-4.552) J3.20@88.42,-4.38
T1_11.T7_P: J3.7 U16.AA8 | length 85.1
  Top Layer w0.127: U16.AA8@9.5,-3.5 v1(10,-3)
  Int7 (Sign) w0.076: v1(10,-3) 10.298,-3 ccw(c10.298,-2.9) 10.398,-2.9 cw(c10.902,-2.9) 10.902,-2.397 16.936,-2.397 cw(c16.936,-6.766) 20.025,-3.676 26.386,-10.037 ccw(c28.469,-7.954) 28.469,-10.9 73.792,-10.9 ccw(c73.792,-8.36) 75.588,-10.156 80.699,-5.045 cw(c82.637,-6.983) 82.637,-4.242 86.53,-4.242 ccw(c86.53,-4.058) 86.661,-4.188 ccw(c86.607,-4.134) 86.683,-4.134 ccw(c86.607,-4.134) 86.661,-4.081 J3.7@85.58,-3
T1_11.T8_N: J3.21 U16.V8 | length 87.4
  Top Layer w0.127: U16.V8@6.5,-3.5 v1(7,-4)
  Int7 (Sign) w0.076: v1(7,-4) cw(c7.398,-4) 7.398,-3.602 16.689,-3.602 cw(c16.689,-7.361) 19.348,-4.703 25.708,-11.063 ccw(c28.223,-8.549) 28.223,-12.105 74.853,-12.105 ccw(c74.853,-9.364) 76.791,-11.302 80.143,-7.95 cw(c81.939,-9.746) 81.939,-7.206 86.595,-7.206 ccw(c86.595,-6.975) 86.759,-7.139 cw(c86.922,-7.302) 86.922,-7.071 88.249,-7.071 cw(c88.249,-7.313) J3.21@88.42,-7.141
T1_11.T8_P: J3.8 U16.V9 | length 87.3
  Top Layer w0.127: U16.V9@6.5,-2.5 v1(7,-3)
  Int7 (Sign) w0.076: v1(7,-3) ccw(c7.398,-3) 7.398,-3.398 16.689,-3.398 cw(c16.689,-7.361) 19.491,-4.559 25.852,-10.92 ccw(c28.223,-8.549) 28.223,-11.902 74.852,-11.902 ccw(c74.852,-9.362) 76.648,-11.158 80,-7.806 cw(c81.938,-9.744) 81.938,-7.003 86.53,-7.003 ccw(c86.53,-6.819) 86.661,-6.949 ccw(c86.607,-6.895) 86.683,-6.895 ccw(c86.607,-6.895) 86.661,-6.842 J3.8@85.58,-5.761
T1_11.T9_N: J3.22 U16.Y7 | length 84.7
  Top Layer w0.127: U16.Y7@8.5,-4.5 v1(9,-5)
  Int7 (Sign) w0.076: v1(9,-5) cw(c9.398,-5) 9.398,-4.602 16.444,-4.602 cw(c16.444,-7.954) 18.814,-5.584 25.175,-11.944 ccw(c27.977,-9.142) 27.977,-13.105 76.047,-13.105 ccw(c76.047,-10.364) 77.985,-12.302 79.576,-10.711 cw(c81.372,-12.507) 81.372,-9.967 86.595,-9.967 ccw(c86.595,-9.736) 86.759,-9.9 cw(c86.922,-10.063) 86.922,-9.832 88.249,-9.832 cw(c88.249,-10.074) J3.22@88.42,-9.902
T1_11.T9_P: J3.9 U16.Y8 | length 84.5
  Top Layer w0.127: U16.Y8@8.5,-3.5 v1(9,-4)
  Int7 (Sign) w0.076: v1(9,-4) ccw(c9.398,-4) 9.398,-4.398 16.444,-4.398 cw(c16.444,-7.954) 18.958,-5.44 25.319,-11.801 ccw(c27.977,-9.142) 27.977,-12.902 76.046,-12.902 ccw(c76.046,-10.362) 77.842,-12.158 79.5,-10.5 cw(c81.276,-12.276) 81.276,-9.764 86.53,-9.764 ccw(c86.53,-9.58) 86.661,-9.71 ccw(c86.607,-9.656) 86.683,-9.656 ccw(c86.607,-9.656) 86.661,-9.603 J3.9@85.58,-8.522
T1_11.T10_N: J3.23 U16.AB6 | length 82
  Top Layer w0.127: U16.AB6@10.5,-5.5 v1(11,-6)
  Int7 (Sign) w0.076: v1(11,-6) cw(c11.398,-6) 11.398,-5.602 16.198,-5.602 cw(c16.198,-8.548) 18.281,-6.465 24.642,-12.825 ccw(c27.731,-9.736) 27.731,-14.105 81.117,-14.105 ccw(c81.117,-11.364) 83.055,-13.302 cw(c84.44,-14.687) 84.44,-12.728 86.595,-12.728 ccw(c86.595,-12.497) 86.759,-12.661 cw(c86.922,-12.824) 86.922,-12.593 88.249,-12.593 cw(c88.249,-12.835) J3.23@88.42,-12.664
T1_11.T10_P: J3.10 U16.AB7 | length 81.8
  Top Layer w0.127: U16.AB7@10.5,-4.5 v1(11,-5)
  Int7 (Sign) w0.076: v1(11,-5) ccw(c11.398,-5) 11.398,-5.398 16.198,-5.398 cw(c16.198,-8.548) 18.425,-6.321 24.785,-12.682 ccw(c27.731,-9.736) 27.731,-13.902 81.116,-13.902 ccw(c81.116,-11.362) 82.912,-13.158 82.965,-13.105 cw(c84.364,-14.504) 84.364,-12.525 86.53,-12.525 ccw(c86.53,-12.341) 86.661,-12.471 ccw(c86.607,-12.417) 86.683,-12.417 ccw(c86.607,-12.417) 86.661,-12.364 J3.10@85.58,-11.283
T1_11.T11_N: J3.24 U16.W7 | length 87.1
  Top Layer w0.127: U16.W7@7.5,-4.5 v1(8,-5)
  Int7 (Sign) w0.076: v1(8,-5) 7.702,-5 cw(c7.702,-4.9) 7.602,-4.9 cw(c7.902,-4.9) 7.902,-4.6 8,-4.6 cw(c8,-5) 8.4,-5 8.4,-6.003 ccw(c9,-6.003) 9,-6.603 15.951,-6.603 cw(c15.951,-9.143) 17.747,-7.347 24.108,-13.708 ccw(c27.484,-10.331) 27.484,-15.106 81.912,-15.106 cw(c81.912,-15.706) 82.337,-15.282 ccw(c82.761,-14.858) 82.761,-15.458 86.649,-15.458 ccw(c86.649,-15.28) 86.774,-15.406 cw(c86.9,-15.531) 86.9,-15.354 88.249,-15.354 cw(c88.249,-15.596) J3.24@88.42,-15.425
T1_11.T11_P: J3.11 U16.V7 | length 87.2
  Top Layer w0.127: U16.V7@6.5,-4.5 v1(7,-5)
  Int7 (Sign) w0.076: v1(7,-5) 7.298,-5 ccw(c7.298,-4.9) 7.398,-4.9 cw(c7.902,-4.9) 7.902,-4.397 8,-4.397 cw(c8,-5) 8.603,-5 8.603,-6.003 ccw(c9,-6.003) 9,-6.4 15.951,-6.4 cw(c15.951,-9.143) 17.891,-7.203 24.251,-13.564 ccw(c27.484,-10.331) 27.484,-14.903 81.997,-14.903 cw(c81.997,-15.503) 82.421,-15.079 ccw(c82.845,-14.655) 82.845,-15.255 86.607,-15.255 ccw(c86.607,-15.178) 86.661,-15.232 ccw(c86.607,-15.178) 86.683,-15.178 ccw(c86.607,-15.178) 86.661,-15.125 J3.11@85.58,-14.044
TCK_FPGA: R22.2 U16.V12 | length 70.3
  Top Layer w0.127: R22.2@-32,38.85 -31.85,39 v1(-31,39) ; U16.V12@6.5,0.5 v1(7,1)
  Int3 (Sign) w0.127: v1(-31,39) -29.244,40.756 cw(c-27.448,38.96) -27.451,41.5 ; -27.5,41.5 -27.451,41.5 ; -27.448,41.5 ccw(c-27.448,38.96) -27.451,41.5 ; v1(7,1) ccw(c7,1.5) 7.5,1.5 7.5,2.5 cw(c8,2.5) 8,3 ccw(c8,3.5) 8.5,3.5 8.5,15.248 ccw(c-5.039,15.248) 4.534,24.822 -8.178,37.534 ccw(c-17.752,27.961) -17.752,41.5 -27.451,41.5
TCK_JTAG: P3.6 R22.1 | length 5.8
  Top Layer w0.203: P3.6@-33,45.5 -32,44.5 R22.1@-32,40.15
TDI_FPGA: R27.2 U16.R13 | length 59.8
  Top Layer w0.127: R27.2@-28,38.85 -27.85,39 v1(-27,39) ; U16.R13@3.5,1.5 v1(4,2)
  Int3 (Sign) w0.127: v1(-27,39) ccw(c-25.793,40.207) -25.793,38.5 -17.752,38.5 cw(c-17.752,27.96) -10.299,35.413 2.413,22.701 cw(c-5.04,15.248) 5.5,15.248 5.5,5 cw(c5,5) 5,4.5 ccw(c5,4) 4.5,4 4.5,2.5 cw(c4,2.5) v1(4,2)
TDI_JTAG: P3.10 R27.1 | length 5.8
  Top Layer w0.203: P3.10@-29,45.5 -28,44.5 R27.1@-28,40.15
TDO_FPGA: R26.2 U16.U13 | length 65.3
  Top Layer w0.127: R26.2@-30,38.85 -29.85,39 v1(-29,39) ; U16.U13@5.5,1.5 v1(6,2)
  Int3 (Sign) w0.127: v1(-29,39) -28.244,39.756 cw(c-26.448,37.96) -26.451,40.5 cw(c-26.448,37.96) -26.448,40.5 -24.5,40.5 -17.752,40.5 cw(c-17.752,27.961) -8.885,36.827 3.827,24.115 cw(c-5.04,15.248) 7.5,15.248 7.5,4 cw(c7,4) 7,3.5 ccw(c7,3) 6.5,3 6.5,2.5 cw(c6,2.5) v1(6,2)
TDO_JTAG: P3.8 R26.1 | length 5.8
  Top Layer w0.203: P3.8@-31,45.5 -30,44.5 R26.1@-30,40.15 R26.1@-30,40.1
TMS_FPGA: R20.2 U16.T13 | length 67.6
  Top Layer w0.127: R20.2@-34,38.85 -33.85,39 v1(-33,39) ; U16.T13@4.5,1.5 v1(5,2)
  Int3 (Sign) w0.127: v1(-33,39) ccw(c-31.793,40.207) -31.793,38.5 -29.207,38.5 ccw(c-29.207,40.207) -28,39 cw(c-26.793,37.793) -26.793,39.5 -17.752,39.5 cw(c-17.752,27.96) -9.592,36.12 3.12,23.408 cw(c-5.04,15.248) 6.5,15.248 6.5,4.5 cw(c6,4.5) 6,4 ccw(c6,3.5) 5.5,3.5 5.5,2.5 cw(c5,2.5) v1(5,2)
TMS_JTAG: P3.4 R20.1 | length 5.8
  Top Layer w0.203: P3.4@-35,45.5 -34,44.5 R20.1@-34,40.15 R20.1@-34,40.1
VCC: C6.1 C12.1 C23.1 C67.1 C86.2 C87.2 C89.2 C91.2 C93.2 C94.2 C95.2 C96.2 C97.2 C98.2 C99.2 C176.2 C192.2 FR1.1 FR3.2 L6.2 L7.2 P6.1 P6.3 P6.5 P6.7 R49.2 R103.2 R104.2 R108.2 R109.2 R110.3 R110.4 R168.1 TP12.1 U1.2 U7.14 U10.14 U13.1 U13.4 U13.10 U13.13 U13.14 U14.9 U14.13 U14.16 U17.13 U17.17 U23.2 U23.4 U23.10 U23.12 U23.14 U25.5 U29.8 U32.8 U33.8 U35.1 U39.1 | length 195.3
  Top Layer w0.203: v3(-57.325,-15.7) U1.2@-57.325,-14.725 ; C6.1@-50.5,26.475 v1(-50.5,27.5) v1(-50.5,28) -48.998,28 -48.95,28.048 U7.14@-48.95,28.275 ; C12.1@-43.5,26.6 v1(-43.5,27.5) v1(-43.5,28) -41.998,28 -41.95,28.048 U10.14@-41.95,28.275 ; v3(-34,-18.325) U14.13@-32.775,-18.325 ; v1(-33.65,21.5) U13.10@-33.65,22.725 ; v3(-33,-20.8) U14.16@-33,-20.3 ; U14.9@-33,-15.7 v3(-33,-15.2) ; U13.4@-33,28.275 v1(-33,29.756) ; U13.13@-31.7,22.725 -31.7,23.352 -31.652,23.4 v1@-30,23.4 ; U13.1@-31.05,28.275 v1(-31.05,29.756) ; U23.10@32.35,7.225 32.398,7.177 32.398,6.184 32.5,6.082 v2(32.5,6) ; v2(33,11.5) v2(33,14.5) ; U23.12@33.65,7.225 v2(33.65,8.402) v2(33.65,8.898) ; v2(34.3,11.5) v2(34.3,14.5) ; U23.14@34.95,7.225 v2(34.95,8.402) v2(34.95,8.9)
  Top Layer w0.4: P6.1@-9.58,42.515 v1@-9.58,44.1 ; P6.3@-8.78,42.515 v1@-8.78,44.1 ; P6.5@-7.98,42.515 v1@-7.98,44.1 ; P6.7@-7.18,42.515 v1@-7.18,44.1
  Top Layer w0.406: U17.13@27.45,5.375 28.497,5.375 v2@28.5,5.372 ; U17.17@27.45,7.975 v2(28.5,7.975) v2(29,7.975) ; v2(28.5,5.375) v2@28.5,5.372 ; v2(29.255,4.613) 29.255,4.617 v2@28.5,5.372 ; C67.1@66,27.525 C67.1@66.3,27.525 v2@67.56,27.525 ; v2(67.5,27.5) cw(c67.56,27.44) v2@67.56,27.525 ; U29.8@68.805,27.525 v2@67.56,27.525
  Int6 (Sign) w0.203: v3(-57.325,-15.7) -57.325,-15.755 -57.2,-15.88 -57.2,-17.4 -58.7,-18.9 -58.7,-31.066 -49.266,-40.5 -35.9,-40.5 -32.1,-36.7 -26.034,-36.7 -22.334,-33 -14.934,-33 -13.134,-31.2 26.9,-31.2 36.1,-40.4 39.773,-40.4 39.973,-40.6 v4(40,-40.6)
  Bottom Layer w0.203: R168.1@-45.2,-19.5 R168.1@-45.15,-19.5 v3(-44.3,-19.5) ; C192.2@-28.475,28.5 -28.002,28.027 -28.002,26.702 U39.1@-27.9,26.6
  Bottom Layer w0.3: C99.2@21,-32.525 21.425,-32.95 21.65,-32.95 v2(22.2,-33.5) 23.025,-34.325 23.525,-34.325 U35.1@23.65,-34.45
  Bottom Layer w0.406: C192.2@-28.5,28.5 v1(-28.5,29.756) ; C176.2@-10.7,44.425 -10.39,44.115 -9.604,44.115 -9.6,44.111 v1@-9.6,44.1 ; C91.2@38.4,46.275 v1(39.5,46.275) U32.8@40.805,46.275 ; C89.2@43.97,38 43.97,38.125 44.598,38.753 44.598,39.518 44.605,39.525 U33.8@45.195,39.525 v1(46.5,39.525) ; v1(56,42.07) R110.3@56.85,42.07 ; v1(56,42.87) R110.4@56.85,42.87 ; R109.2@59,-24.35 59.02,-24.37 59.721,-24.37 60.9,-25.549 R108.2@60.9,-27.05 ; v1(90,37.5) R103.2@91.05,37.5 ; v1(90,44.5) R104.2@91.05,44.5
  Bottom Layer w0.5: C86.2@47.675,36 47.675,36.125 49.05,37.5 49.6,37.5 L6.2@50,37.9 ; C87.2@47.675,49.7 47.675,49.575 49.05,48.2 49.6,48.2 L7.2@50,47.8
  other v1: -30.1,23 -29.6,23 -29.1,23 -30.1,23.5 -29.6,23.5 -29.1,23.5 -50.5,28.5 -43.5,28.5 51.5,37.6 51.5,38.2 -9.568,44.1 -8.768,44.1 -7.968,44.1 -7.168,44.1 51.5,47.5 51.5,48.1
  other v2: 54.6,-9.3 54.6,-8.7 28.864,5 23.5,6.5 25.5,6.5 24.2,7 23.5,8 39.05,10.025 40,11.5
  other v3: -27.5,4.1 -27.5,4.5 -27.5,4.9
  other v4: 58.8,-23.5 59.1,-23.5
VCC1V8: C100.2 C104.2 C105.2 C112.2 C135.2 C138.2 C145.2 C149.2 C159.2 L1.2 L8.2 R48.2 R123.2 TP10.1 U6.2 U16.H12 U16.K12 U16.M12 U16.P12 U16.R11 | length 135.8
  Top Layer w0.127: v1(-4,1) U16.H12@-3.5,0.5 ; v1(-2,1) U16.K12@-1.5,0.5 ; U16.M12@0.5,0.5 v1(1,1) ; U16.P12@2.5,0.5 v1(3,1) ; U16.R11@3.5,-0.5 v1(4,-1)
  Top Layer w0.203: U6.2@-49.325,-14.725 -49.321,-14.729 v3(-49.321,-15.7) ; v4(39.2,-21.9) 39.219,-21.919 39.269,-21.919 40.35,-23 R48.2@40.9,-23
  Top Layer w0.508: R48.2@40.9,-23 41,-23.1 TP10.1@41,-25.5
  Int6 (Sign) w0.203: v3(-49.321,-15.7) -49.321,-15.754 -49.2,-15.876 -49.2,-17.3 -51.7,-19.8 -51.7,-30.6 -50.1,-32.2 -40.534,-32.2 -33.606,-25.272 -14.994,-25.272 -12.066,-28.2 27.997,-28.2 34.397,-21.8 39.073,-21.8 39.173,-21.9 v4(39.2,-21.9)
  Bottom Layer w0.508: TP10.1@41,-25.5 41.242,-25.5 cw(c41.242,-28.04) 43.038,-26.244 48.606,-31.812 cw(c46.81,-33.608) 49.35,-33.608 R123.2@49.35,-33.75
  other v1: 5,-16.6 6,-16 -14.8,-9.8 -14.8,-9.3 -14.8,-8.7 -14.8,-8.2 12.5,-0.3 13,-0.3 13.5,-0.3 14,-0.3 14.5,-0.3 15,-0.3 16.5,0.1
VCC2: C5.1 C19.2 C199.1 C202.1 C204.1 C206.1 FR1.2 R16.1 R167.1 R179.1 R191.1 R197.1 U2.1 U2.18 U5.7 U6.7 U8.7 U9.7 U15.1 | length 25
  Top Layer w0.203: U5.7@-53.325,-10.275 U5.7@-53.312,-10.288 ; v3(-53.3,-11.5) -53.312,-11.488 U5.7@-53.312,-10.288 ; U5.7@-53.3,-10.3 U5.7@-53.312,-10.288 ; v3(-53.275,-5.3) U2.18@-53.275,-3.925 ; U6.7@-49.325,-10.275 -49.318,-10.275 v3(-49.318,-11.5) ; v3(-45.325,-11.5) U8.7@-45.325,-10.275 ; v3(-39.2,-3.5) -39.145,-3.5 -38.87,-3.775 U9.7@-37.775,-3.775 ; C19.2@-34.95,2.475 -34.775,2.3 v3(-34,2.3) ; v3@-34,2.275 U15.1@-32.775,2.275
  Top Layer w0.3: v3@-48.6,4.5 -47.8,4.5 -46.775,3.475 U2.1@-46.775,1.925
  Top Layer w0.5: C19.2@-34.95,2.475 -34.95,4.45 -34.45,4.95 v3@-34.4,5
  Bottom Layer w0.203: R197.1@-57,-12.55 R197.1@-56.675,-12.225 ; R197.1@-56.7,-12.2 R197.1@-56.675,-12.225 ; v3(-56.675,-11.5) R197.1@-56.675,-12.225 ; C206.1@-53.8,-10.2 C206.1@-53.85,-10.2 -53.85,-10.95 v3(-53.3,-11.5) -53.3,-12.25 R191.1@-53,-12.55 ; C204.1@-49.85,-10.2 -49.85,-10.968 v3(-49.318,-11.5) -49.318,-12.332 R179.1@-49,-12.65 ; C202.1@-45.85,-10.2 -45.85,-10.975 v3(-45.325,-11.5) -45.325,-12.325 R167.1@-45,-12.65
  other v3: -41.7,-9.2 -41.3,-9.2 -39.2,-3 -48.614,4.1 -48.614,4.5 -48.614,4.9 -34.5,5 -34,5 -33.5,5
VCCINT: C101.2 C102.2 C106.2 C107.2 C108.2 C116.2 C117.2 C118.2 C129.1 C131.1 C133.1 C136.1 C137.1 C139.1 C140.2 C143.1 C144.1 C151.1 C153.2 C155.1 C156.1 C157.1 C160.1 R96.2 R125.2 TP22.1 U5.2 U16.H8 U16.H10 U16.J7 U16.J9 U16.J11 U16.K8 U16.L7 U16.L11 U16.M8 U16.N7 U16.N11 U16.P8 U16.P10 U16.R7 U16.R9 U16.T8 U16.T10 | length 204.5
  Top Layer w0.127: v1(-4,-4) U16.H8@-3.5,-3.5 ; v1(-4,-2) U16.H10@-3.5,-1.5 ; v1(-3,-5) U16.J7@-2.5,-4.5 ; v1(-3,-3) U16.J9@-2.5,-2.5 ; v1(-3,-1) U16.J11@-2.5,-0.5 ; v1(-2,-4) U16.K8@-1.5,-3.5 ; v1(-1,-5) U16.L7@-0.5,-4.5 ; v1(-1,-1) U16.L11@-0.5,-0.5 ; U16.M8@0.5,-3.5 v1(1,-4) ; U16.N7@1.5,-4.5 v1(2,-5) ; U16.N11@1.5,-0.5 v1(2,-1) ; U16.P8@2.5,-3.5 v1(3,-4) ; U16.P10@2.5,-1.5 v1(3,-2) ; U16.R7@3.5,-4.5 v1(4,-5) ; U16.R9@3.5,-2.5 v1(4,-3) ; U16.T8@4.5,-3.5 v1(5,-4) ; U16.T10@4.5,-1.5 v1(5,-2)
  Top Layer w0.203: v3(-53.325,-15.7) U5.2@-53.325,-14.725
  Int3 (Sign) w0.203: v4(49.3,-23.6) 49.956,-24.256 ccw(c51.752,-22.46) 51.752,-25 62.46,-25 cw(c62.46,-27.54) 65,-27.54 TP22.1@65,-42.238
  Int6 (Sign) w0.203: v3(-53.325,-15.7) -53.325,-15.755 -53.2,-15.88 -53.2,-17.6 -55.5,-19.9 -55.5,-25.366 -54,-26.866 -54,-31.766 -51.066,-34.7 -34.9,-34.7 -33.146,-32.946 -24.581,-32.946 -23.034,-31.4 -15.834,-31.4 -14.094,-29.66 27.394,-29.66 35.934,-38.2 60.534,-38.2 62.834,-40.5 66.272,-40.5 66.472,-40.7 v4(66.5,-40.7)
  Bottom Layer w0.127: C157.1@-3.096,-2.996 C157.1@-3,-2.9 ; v1@1.83,-1 1.85,-1 C140.2@1.997,-1.147
  Bottom Layer w0.35: v1(9.8,-18.5) C116.2@9.8,-17.4 ; v1(9.8,-16.4) C117.2@9.8,-15.4 ; v1(9.8,-14.4) C118.2@9.8,-13.5 ; C116.2@10.5,-17.3 v1(10.5,-16.4) ; C117.2@10.5,-15.3 v1(10.5,-14.4) ; C118.2@10.5,-13.5 v1(10.5,-12.5) ; v1(13.3,-18.5) 13.3,-17.725 13.625,-17.4 C106.2@13.65,-17.4 13.675,-17.4 14,-17.075 v1(14,-16.4) ; v1(13.3,-16.4) 13.3,-15.725 13.625,-15.4 C107.2@13.65,-15.4 13.675,-15.4 14,-15.075 v1(14,-14.4) ; v1(13.3,-14.4) 13.3,-13.725 13.625,-13.4 C108.2@13.65,-13.4 13.675,-13.4 14,-13.075 v1(14,-12.5)
  other v1: 15,-17.4 15,-16.9 15,-14.1 15,-13.6
VDD: C31.2 C32.2 C40.2 C103.2 C109.2 C110.2 C111.2 C113.2 C114.2 C115.2 C119.2 C120.2 C121.2 C122.2 C123.2 C124.2 C125.2 C126.2 C127.2 C130.2 C132.2 C134.2 C141.2 C142.2 C147.2 C150.2 C154.2 C158.2 C162.2 C163.2 C164.2 C167.2 C168.2 C169.2 C171.2 C172.2 C175.2 C177.2 C178.2 C179.2 C180.2 C182.2 C183.2 C188.1 FR2.2 P3.2 P5.74 P5.76 P6.73 P6.75 R21.1 R25.2 R29.2 R32.2 R33.2 R34.1 R38.1 R40.2 R42.1 R43.2 R44.2 R61.2 R62.1 R72.2 R83.1 R97.2 R111.2 R112.2 R113.2 R116.1 R130.2 R133.2 R134.2 R156.2 R186.1 TP21.1 U8.2 U16.A17 U16.AA7 U16.AA17 U16.AB4 U16.AB14 U16.B14 U16.C1 U16.C21 U16.D18 U16.E15 U16.F2 U16.F12 U16.F22 U16.G19 U16.H6 U16.H16 U16.J3 U16.J13 U16.K20 U16.L17 U16.M4 U16.M14 U16.N1 U16.N21 U16.P18 U16.R5 U16.R15 U16.T2 U16.T12 U16.T22 U16.U19 U16.V6 U16.V16 U16.W3 U16.W13 U16.Y10 U16.Y20 U18.2 U20.8 U22.10 U26.8 U38.1 Y1.4 | length 239.9
  Top Layer w0.127: v1(-11,6) U16.A17@-10.5,5.5 ; v1(-10,3) U16.B14@-9.5,2.5 ; v1(-9,-11) U16.C1@-8.5,-10.5 ; v1(-9,10) U16.C21@-8.5,9.5 ; v1(-8,7) U16.D18@-7.5,6.5 ; v1(-7,4) U16.E15@-6.5,3.5 ; v1(-6,-10) U16.F2@-5.5,-9.5 ; v1(-6,1) U16.F12@-5.5,0.5 ; v1(-6,11) U16.F22@-5.5,10.5 ; v1(-5,8) U16.G19@-4.5,7.5 ; v1(-4,-6) U16.H6@-3.5,-5.5 ; v1(-4,5) U16.H16@-3.5,4.5 ; v1(-3,-9) U16.J3@-2.5,-8.5 ; v1(-3,2) U16.J13@-2.5,1.5 ; v1(-2,9) U16.K20@-1.5,8.5 ; v1(-1,6) U16.L17@-0.5,5.5 ; U16.M4@0.5,-7.5 v1(1,-8) ; U16.M14@0.5,2.5 v1(1,3) ; U16.N1@1.5,-10.5 v1(2,-11) ; U16.N21@1.5,9.5 v1(2,10) ; U16.P18@2.5,6.5 v1(3,7) ; U16.R5@3.5,-6.5 v1(4,-7) ; U16.R15@3.5,3.5 v1(4,4) ; U16.T2@4.5,-9.5 v1(5,-10) ; U16.T12@4.5,0.5 v1(5,1) ; U16.T22@4.5,10.5 v1(5,11) ; U16.U19@5.5,7.5 v1(6,8) ; U16.V6@6.5,-5.5 v1(7,-6) ; U16.V16@6.5,4.5 v1(7,5) ; U16.W3@7.5,-8.5 v1(8,-9) ; U16.W13@7.5,1.5 v1(8,2) ; U16.Y10@8.5,-1.5 v1(9,-2) ; U16.Y20@8.5,8.5 v1(9,9) ; v1(9,5) U16.AA17@9.5,5.5 ; U16.AA7@9.5,-4.5 v1(10,-5) ; U16.AB4@10.5,-7.5 v1(11,-8) ; U16.AB14@10.5,2.5 v1(11,3)
  Top Layer w0.203: U8.2@-45.325,-14.725 -45.325,-15.675 v3@-45.3,-15.7 ; R21.1@-32.35,-8 R25.2@-30.65,-8 -30.6,-8 cw(c-30.6,-8.1) R25.2@-30.5,-8.1 ; Y1.4@25.4,16.1 25.5,16 v1(27.5,16) ; v2(29.8,2.5) U22.10@30.95,2.5 ; C40.2@46.834,-30.941 47.025,-30.75 48.712,-30.75 49.212,-31.25 U26.8@50.075,-31.25 ; R61.2@49.15,-43 R62.1@49.15,-42.047 ; R72.2@54.15,-43 v4(54.15,-42.35)
  Top Layer w0.3: C31.2@34.77,24.825 R43.2@36.07,26.095 ; v4(57.3,-42.45) R83.1@57.85,-43
  Top Layer w0.35: v1(19.085,32.445) R33.2@20,32.445 ; v1(23.21,44.051) cw(c23.185,44.026) 23.22,44.026 P6.73@23.22,42.515 ; v1(23.22,-24.5) P5.74@23.22,-22.875 ; v1(24.02,-24.5) P5.76@24.02,-22.875 ; P6.75@24.02,42.515 v1(24.02,44.051) ; U20.8@30,24.7 v1(30.9,24.7) U18.2@32,24.7 ; R40.2@30.555,22 v1(31.42,22) ; U18.2@32.6,24.825 C31.2@34.77,24.825 ; R42.1@36.07,31.175 v1(37.02,31.175) ; R44.2@36.07,32.445 v1(37.02,32.445)
  Top Layer w0.406: C32.2@34.77,23.555 C31.2@34.77,24.825 ; R62.1@49.1,-42 49.103,-42 R62.1@49.15,-42.047 ; R83.1@57.85,-43 R83.1@57.95,-43
  Int6 (Sign) w0.203: v3(-45.325,-15.7) -45.325,-15.754 -45.2,-15.879 -45.2,-21.634 -50.2,-26.634 -50.2,-29.866 -49.366,-30.7 -40.534,-30.7 -33.334,-23.5 -14.3,-23.5 -13.1,-24.7 -10.934,-24.7 -10.134,-23.9 17.9,-23.9 23.2,-18.6 40,-18.6 46.6,-25.2 68.166,-25.2 69.2,-24.166 69.2,-22.3 68.1,-21.2 66.728,-21.2 66.528,-21 v4(66.5,-21)
  Bottom Layer w0.127: v1(9,9) C115.2@9.67,9
  Bottom Layer w0.203: R186.1@-51,-4.35 -51,-4.4 -48.2,-7.2 -47.644,-7.756 ccw(c-45.848,-5.96) -47.642,-7.758 ccw(c-45.848,-5.96) -45.848,-8.5 -32.707,-8.5 ccw(c-32.707,-6.793) -31.502,-8.002 ccw(c-32.707,-6.793) v3(-31.5,-8) ; R130.2@15.65,-5.5 15.887,-5.737 16.237,-5.737 v1(16.5,-6) ; R133.2@15.65,-2.5 15.887,-2.737 16.237,-2.737 v1(16.5,-3) ; R134.2@15.65,-1.5 15.887,-1.737 16.237,-1.737 v1(16.5,-2) ; v4(55.8,-41.95) R116.1@56.5,-41.95
  Bottom Layer w0.3: C188.1@-20.85,-35.5 -19.65,-35.5 U38.1@-19.65,-35.05 v6(-19.65,-34) v6(-19.65,-33.5)
  Bottom Layer w0.406: v1(56,40.47) R111.2@56.85,40.47 ; v1(56,44.47) R112.2@56.85,44.47 ; v1(56,46.07) R113.2@56.85,46.07
  Bottom Layer w0.5: R156.2@-39.35,45.5 P3.2@-37,45.5
  other v1: 5,3 5,5 -14.9,13.5 6,14.3 -10.4,14.4 13.4,14.4 -14.9,14.5 -13.9,14.5 -13.4,14.5 13.9,14.5 14.9,14.5 9.9,14.6 14.9,15.7 9.9,16.4 10.4,16.4 -14.9,16.5 -13.9,16.5 -13.4,16.5 -14.9,18 13.3,18.2 9.9,18.3 10.4,18.3 -13.9,18.4 -13.4,18.4 -10.4,18.4 -9.9,18.4 13.3,18.7 13.8,18.7 9.9,18.8 10.4,18.8 -13.9,18.9 -13.4,18.9 -10.4,18.9 -9.9,18.9 19.085,23.555 19.085,24.825
  other v3: -20.6,0.8 -20.2,0.8
  other v4: 49.15,-42.45 46.312,-31.687 46.562,-31.687
VREF2V5: C7.1 C13.1 C15.1 C17.1 C203.2 R9.1 R13.1 TP3.1 U11.3 U12.3 U42.6 | length 25.1
  Top Layer w0.203: C13.1@-42.975,-27.975 C13.1@-43.1,-27.975 v3(-43.1,-28.8) -42.902,-28.998 -42.384,-28.998 -42.383,-29 -41.7,-29 -40.375,-30.325 U12.3@-39.2,-30.325 ; U11.3@-39.2,-39.825 -38.275,-39.825 -38,-40.1 C17.1@-38,-42
  Bottom Layer w0.406: -43.365,-28.545 U42.6@-43.365,-26.95
  Bottom Layer w1.5: v3(-50.7,-36) -50.6,-36 -44.1,-42.5 v3(-39.5,-42.5) -38.6,-42.5
  other v3: -39.5,-42.9 -39.5,-42.1 -50.7,-36.4 -50.7,-35.6 -43.5,-33 -43.1,-33 -42.7,-33 -43.5,-28.8 -42.7,-28.8
VREF-PH: C54.2 C55.1 C62.2 C82.2 R79.2 U24.3 U28.5 U31.6 | length 29.6
  Top Layer w0.203: U24.3@42.4,4.135 43.2,4.135 43.565,4.5 53.933,4.5 53.934,4.499 54.051,4.499 C54.2@54.525,4.025 ; C54.2@54.525,3.9 C54.2@54.525,4.025 ; C55.1@56.002,5.5 R79.2@56.002,7.948 ; R79.2@56.45,7.5 R79.2@56.002,7.948 ; C55.1@56.475,5.5 57.4,5.5 58.375,6.475 C62.2@58.5,6.475 ; C55.1@56.475,5.7 56.475,5.575 55.7,4.8 55.3,4.8 C54.2@54.525,4.025 ; U28.5@57.9,9.095 56.178,9.095 56.084,9.002 v2(56,9) R79.2@56.002,7.948
  Bottom Layer w0.203: U31.6@52.9,10.365 54.635,10.365 55.9,9.1 v2@56,9.1 ; C82.2@55,7.3 55,8 v2(56,9)
VREG: C52.1 FR6.1 R117.2 R120.2 R121.2 R189.1 TP15.1 U26.23 U26.44 | length 148.1
  Top Layer w0.203: C52.1@52.625,-25.775 52.75,-25.9 U26.44@52.75,-27.075 ; U26.23@55.75,-33.925 55.759,-33.935 v4(55.759,-34.5)
  Int6 (Sign) w0.508: v3(-54.1,-8.7) v3(-53.7,-8.7) -53.7,-8.8 -49,-13.5 -24.3,-13.5 -18.1,-19.7 14.1,-19.7 18.8,-15 51.5,-15 53.5,-17 TP15.1@53.5,-19.75
  Int2 (Sign) w0.203: v4(52.813,-26.437) ccw(c53.875,-26.437) 53.875,-27.5 55.5,-27.5 cw(c55.5,-28.4) 56.4,-28.4 56.4,-33.859 cw(c55.759,-33.859) v4(55.759,-34.5)
  Bottom Layer w0.203: FR6.1@-53.9,-7.5 -53.202,-6.802 -53.202,-6.027 -52.5,-5.325 R189.1@-52.5,-4.35 ; R121.2@51.3,-24.35 R120.2@52.5,-25.65 52.748,-25.898 52.748,-26.346 52.813,-26.41 v4(52.813,-26.437)
  Bottom Layer w0.508: R121.2@51.3,-24.35 51.3,-23.002 cw(c53.84,-23.002) 52.044,-21.206 TP15.1@53.5,-19.75 54.956,-21.206 cw(c53.16,-23.002) 55.7,-23.002 R117.2@55.7,-24.35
